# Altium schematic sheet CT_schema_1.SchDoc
size 500 x 258 mm
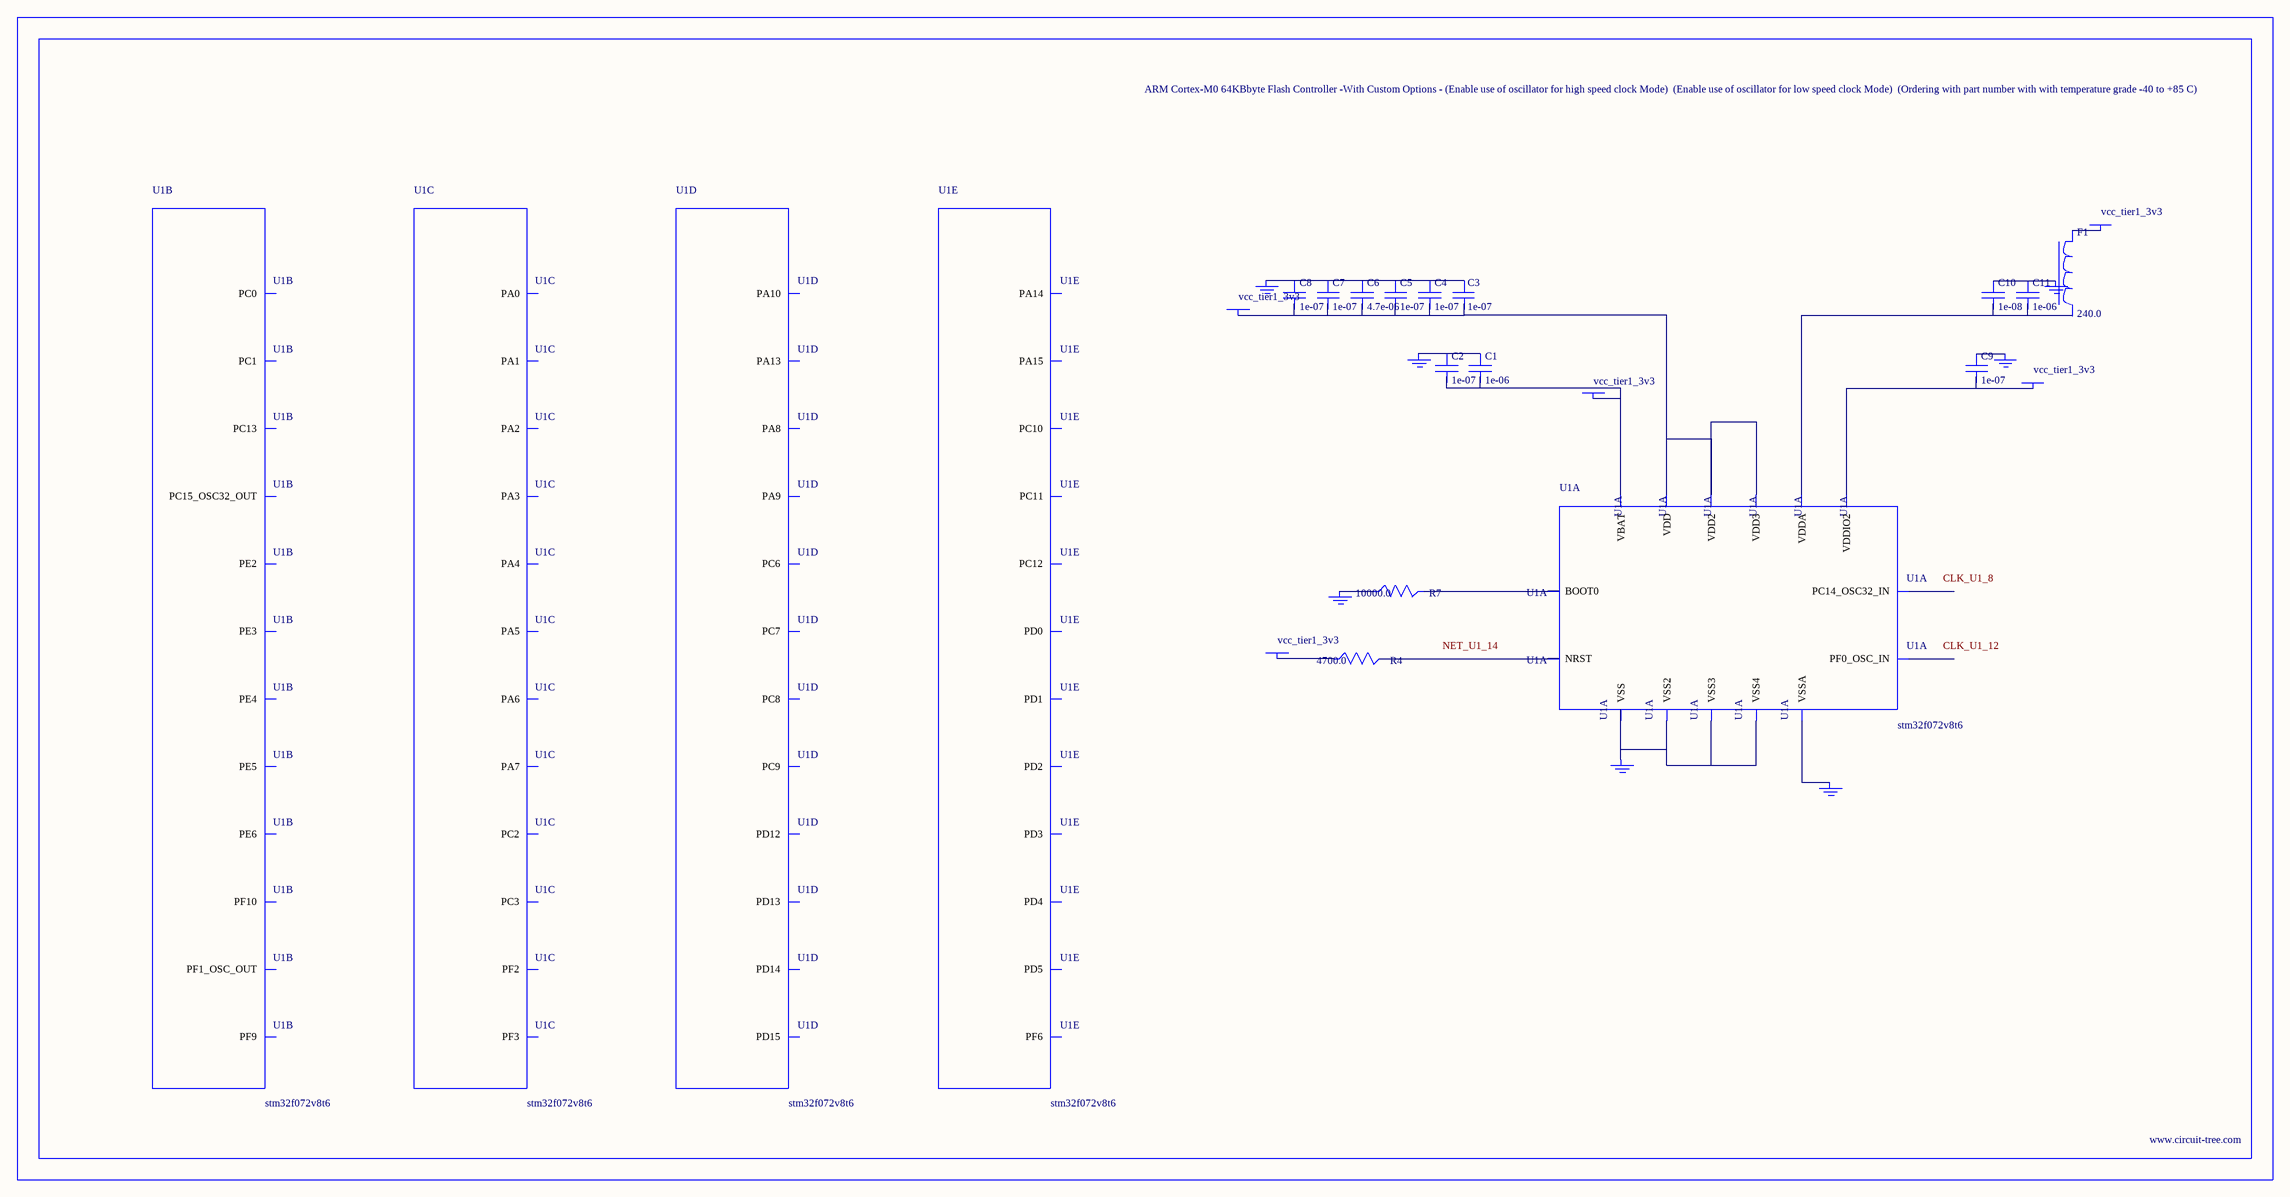
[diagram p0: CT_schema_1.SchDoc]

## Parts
BORDER0  (no value)
C1  1e-06  [C0603]
C2  1e-07  [C0603]
C3  1e-07  [C0603]
C4  1e-07  [C0603]
C5  1e-07  [C0603]
C6  4.7e-06  [C0603]
C7  1e-07  [C0603]
C8  1e-07  [C0603]
C9  1e-07  [C0603]
C10  1e-08  [C0603]
C11  1e-06  [C0603]
F1  240.0  [L0603]
GND_INSTANCE_0_0  (no value)
GND_INSTANCE_0_1  (no value)
GND_INSTANCE_0_2  (no value)
GND_INSTANCE_0_3  (no value)
GND_INSTANCE_0_4  (no value)
GND_INSTANCE_0_5  (no value)
GND_INSTANCE_0_6  (no value)
POWER_INSTANCE_0_0  vcc_tier1_3v3
POWER_INSTANCE_0_1  vcc_tier1_3v3
POWER_INSTANCE_0_2  vcc_tier1_3v3
POWER_INSTANCE_0_3  vcc_tier1_3v3
POWER_INSTANCE_0_4  vcc_tier1_3v3
R4  4700.0  [R0603]
R7  10000.0  [R0603]
U1  stm32f072v8t6  [LQFP100]  (parts A,B,C,D,E of 9)

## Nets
NetC1_1: C1.1 C2.1 GND_INSTANCE_0_0.0(GND)
NetC1_2: C1.2 C2.2 POWER_INSTANCE_0_0.0(PWR) U1.6(VBAT)
NetC3_1: C3.1 C4.1 C5.1 C6.1 C7.1 C8.1 GND_INSTANCE_0_3.0(GND)
NetC3_2: C3.2 C4.2 C5.2 C6.2 C7.2 C8.2 POWER_INSTANCE_0_2.0(PWR) U1.28(VDD) U1.50(VDD2) U1.100(VDD3)
NetC9_1: C9.1 GND_INSTANCE_0_4.0(GND)
NetC9_2: C9.2 POWER_INSTANCE_0_3.0(PWR) U1.75(VDDIO2)
NetC10_1: C10.1 C11.1 GND_INSTANCE_0_2.0(GND)
NetC10_2: C10.2 C11.2 U1.21(VDDA)
NetF1_1: F1.1 POWER_INSTANCE_0_1.0(PWR)
NetGND_INSTANCE_0_1_0: GND_INSTANCE_0_1.0(GND) U1.20(VSSA)
NetGND_INSTANCE_0_5_0: GND_INSTANCE_0_5.0(GND) R7.1
NetGND_INSTANCE_0_6_0: GND_INSTANCE_0_6.0(GND) U1.27(VSS) U1.49(VSS2) U1.74(VSS3) U1.99(VSS4)
NetPOWER_INSTANCE_0_4_0: POWER_INSTANCE_0_4.0(PWR) R4.1
NetR4_2: R4.2 U1.14(NRST)
NetR7_2: R7.2 U1.94(BOOT0)

Not connected (* = marked no-connect by the designer): F1 2; U1 1(PE2) 2(PE3) 3(PE4) 4(PE5) 5(PE6) 7(PC13) 8(PC14_OSC32_IN) 9(PC15_OSC32_OUT) 10(PF9) 11(PF10) 12(PF0_OSC_IN) 13(PF1_OSC_OUT) 15(PC0) 16(PC1) 17(PC2) 18(PC3) 19(PF2) 22(PF3) 23(PA0) 24(PA1) 25(PA2) 26(PA3) 29(PA4) 30(PA5) 31(PA6) 32(PA7) 59(PD12) 60(PD13) 61(PD14) 62(PD15) 63(PC6) 64(PC7) 65(PC8) 66(PC9) 67(PA8) 68(PA9) 69(PA10) 72(PA13) 73(PF6) 76(PA14) 77(PA15) 78(PC10) 79(PC11) 80(PC12) 81(PD0) 82(PD1) 83(PD2) 84(PD3) 85(PD4) 86(PD5)

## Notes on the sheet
- Labels drawn without touching a wire or pin: CLK_U1_8, CLK_U1_12, NET_U1_14

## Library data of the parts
BORDER0 = BORDER_PAGE0
C1 C11 = C0603C105K3RACTU
C2-C5 C7-C9 = 06035C104K4Z2A
C6 = GRM188R6YA475KE15D
C10 = 06035C103K4Z2A
F1 = Z0603C241ASMST
GND_INSTANCE_0_0-GND_INSTANCE_0_6 = GND
POWER_INSTANCE_0_0-POWER_INSTANCE_0_4 = PWR
R4 = RC0603JR-074K7L
R7 = RC0603JR-0710KL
